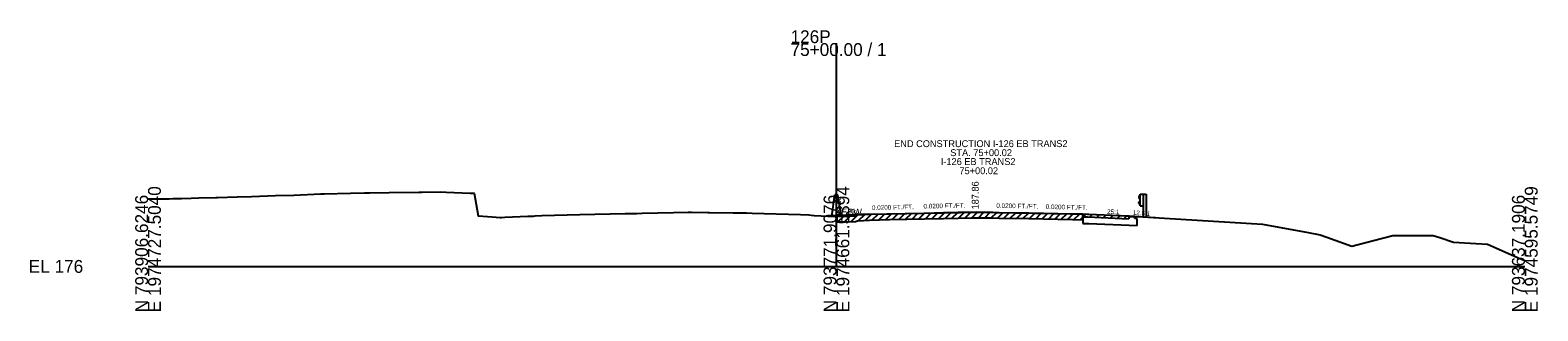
# Model space of a CAD drawing. Extents: x -161 to 1970889, y -4362 to 797231.
# Drawn here: x 2974.3 to 3302.8, y 5990.3 to 6051.5 of the extents above; entities that cross this region are included whole.
import ezdxf

# ---------------------------------------------------------------- set-up
doc = ezdxf.new("R2010")
doc.units = 0
for name, color, linetype in [('RD_GPK_XS_Cell', 7, 'Continuous'), ('RD_XS_Base', 7, 'Continuous'), ('RD_XS_EarthShd', 7, 'Continuous'), ('RD_XS_ExGround', 7, 'Continuous'), ('RD_XS_ExPaveRet', 7, 'Continuous'), ('RD_XS_GR', 7, 'Continuous'), ('RD_XS_MedBWall', 7, 'Continuous'), ('RD_XS_Misc_Line', 7, 'Continuous'), ('RD_XS_Pave', 7, 'Continuous'), ('RD_XS_PaveOvlay', 7, 'Continuous'), ('RD_XS_PaveShd', 7, 'Continuous'), ('RD_XS_TieSlope', 7, 'Continuous'), ('RD_XS_TX_Elev_EX', 7, 'Continuous'), ('RD_XS_TX_Elev_PR', 7, 'Continuous'), ('RD_XS_TX_MkPT', 7, 'Continuous'), ('RD_XS_TX_Notes', 7, 'Continuous'), ('RD_XS_TX_Profile', 7, 'Continuous'), ('RD_XS_TX_ShdSlope', 7, 'Continuous'), ('RD_XS_TX_Slope', 7, 'Continuous'), ('RD_XS_TX_Station', 7, 'Continuous')]:
    doc.layers.add(name, color=color, linetype=linetype)

msp = doc.modelspace()

# ---------------------------------------------------------------- linework, layer by layer
at = {"layer": 'RD_GPK_XS_Cell'}
for p, q in [((3150, 6000), (3150, 6048.68)), ((3000, 6000), (3150, 6000)), ((3150, 6000), (3300, 6000))]:
    msp.add_line(p, q, dxfattribs=at)
at = {"layer": 'RD_XS_Base'}
for p, q in [((3203.71, 6009.37), (3205, 6009.34)), ((3205, 6009.34), (3215.5, 6008.92)), ((3215, 6010.42), (3215, 6010.98)), ((3215.5, 6010.4), (3215, 6010.42)), ((3215.5, 6008.92), (3215.5, 6010.4))]:
    msp.add_line(p, q, dxfattribs=at)
at = {"layer": 'RD_XS_EarthShd'}
msp.add_line((3215, 6010.98), (3217, 6010.82), dxfattribs=at)
at = {"layer": 'RD_XS_ExGround'}
msp.add_lwpolyline([(3000, 6014.7), (3004.58, 6014.77), (3005.41, 6014.78), (3007.27, 6014.82), (3009.39, 6014.87), (3011.07, 6014.93), (3014.78, 6015.01), (3015.15, 6015.01), (3019.39, 6015.15), (3022.51, 6015.25), (3026.03, 6015.37), (3027.76, 6015.43), (3031.78, 6015.57), (3037.68, 6015.79), (3038.41, 6015.8), (3044.14, 6015.94), (3047.13, 6016.02), (3047.79, 6016.05), (3048.31, 6016.06), (3052.55, 6016.1), (3059.02, 6016.18), (3059.75, 6016.17), (3063.68, 6016.23), (3064.96, 6016.17), (3070.16, 6015.97), (3070.55, 6015.97), (3071.03, 6015.97), (3071.9, 6011), (3074.98, 6010.79), (3076.73, 6010.64), (3077.04, 6010.67), (3077.71, 6010.75), (3082.75, 6010.92), (3084.01, 6010.96), (3084.32, 6011.06), (3085.79, 6011.1), (3094.11, 6011.34), (3103.96, 6011.52), (3106.48, 6011.57), (3107.69, 6011.59), (3114.51, 6011.75), (3117.66, 6011.83), (3118.44, 6011.85), (3121.99, 6011.79), (3122.31, 6011.79), (3127.48, 6011.7), (3130.37, 6011.65), (3131.62, 6011.61), (3142.19, 6011.34), (3143.95, 6011.23), (3144.47, 6011.19), (3145.18, 6011.07), (3146.65, 6011.02), (3148.12, 6010.97), (3150, 6010.96), (3151.07, 6010.95), (3151.94, 6010.98), (3154.12, 6011.04), (3154.58, 6011.22), (3157.23, 6011.36), (3161.58, 6011.46), (3169.17, 6011.64), (3173.3, 6011.73), (3176.56, 6011.8), (3179.39, 6011.85), (3180.44, 6011.87), (3183.55, 6011.83), (3184.09, 6011.81), (3185.44, 6011.79), (3191.91, 6011.66), (3201.44, 6011.48), (3204.68, 6011.41), (3213.71, 6011.01), (3214.05, 6010.9), (3215.58, 6010.87), (3217.91, 6010.72), (3242.87, 6009.24), (3252.82, 6007.39), (3255.4, 6006.9), (3256.87, 6006.35), (3262.33, 6004.42), (3267, 6005.63), (3271.27, 6006.76), (3273.64, 6006.76), (3280.05, 6006.76), (3281.48, 6006.29), (3284.47, 6005.28), (3289.34, 6005.01), (3291.89, 6004.84), (3298.26, 6002.04), (3298.58, 6001.9), (3300, 6001.31)], dxfattribs=at)
at = {"layer": 'RD_XS_ExPaveRet'}
for p, q in [((3150, 6009.71), (3150, 6010.96)), ((3203.71, 6010.81), (3203.71, 6011.43)), ((3203.71, 6011.43), (3203.71, 6010.18)), ((3203.71, 6010.81), (3204.68, 6010.79)), ((3204.68, 6010.79), (3213.71, 6010.38)), ((3213.71, 6011.01), (3213.71, 6010.38)), ((3213.71, 6010.38), (3213.71, 6010.38))]:
    msp.add_line(p, q, dxfattribs=at)
msp.add_lwpolyline([(3150, 6009.71), (3150, 6009.71), (3151.07, 6009.7), (3151.94, 6009.73), (3154.12, 6009.79), (3154.58, 6009.97), (3157.23, 6010.11), (3161.58, 6010.21), (3169.17, 6010.39), (3173.3, 6010.48), (3176.56, 6010.55), (3179.39, 6010.6), (3180.44, 6010.62), (3183.55, 6010.58), (3184.09, 6010.56), (3185.44, 6010.54), (3191.91, 6010.41), (3201.44, 6010.23), (3203.71, 6010.18)], dxfattribs=at)
at = {"layer": 'RD_XS_GR'}
for p, q in [((3216.15, 6015.61), (3215.88, 6015.17)), ((3216.15, 6015.77), (3216.81, 6015.77)), ((3216.15, 6013.21), (3216.15, 6015.77)), ((3216.81, 6015.77), (3217.48, 6015.77)), ((3216.81, 6015.77), (3216.81, 6010.83)), ((3217.48, 6015.77), (3217.48, 6010.72)), ((3215.88, 6015.17), (3215.88, 6015.06)), ((3215.88, 6015.06), (3216.15, 6014.62)), ((3215.88, 6013.92), (3216.15, 6014.36)), ((3215.88, 6013.81), (3215.88, 6013.92)), ((3216.15, 6013.37), (3215.88, 6013.81)), ((3216.15, 6013.21), (3216.81, 6013.21))]:
    msp.add_line(p, q, dxfattribs=at)
at = {"layer": 'RD_XS_MedBWall'}
for p, q in [((3148.98, 6010.97), (3149.67, 6015.6)), ((3150, 6015.6), (3149.67, 6015.6)), ((3150, 6015.6), (3150.33, 6015.6)), ((3151, 6011.12), (3150.33, 6015.6))]:
    msp.add_line(p, q, dxfattribs=at)
at = {"layer": 'RD_XS_Misc_Line'}
for p, q in [((3150, 6010.8), (3150.16, 6010.96)), ((3150.32, 6009.71), (3151.58, 6010.97)), ((3151.75, 6009.72), (3153.04, 6011.01)), ((3153.21, 6009.77), (3154.67, 6011.23)), ((3154.84, 6009.98), (3156.16, 6011.3)), ((3156.33, 6010.06), (3157.63, 6011.37)), ((3157.8, 6010.12), (3159.08, 6011.4)), ((3159.25, 6010.15), (3160.53, 6011.43)), ((3160.7, 6010.19), (3161.98, 6011.47)), ((3162.15, 6010.22), (3163.43, 6011.5)), ((3163.6, 6010.26), (3164.88, 6011.54)), ((3165.05, 6010.29), (3166.32, 6011.57)), ((3166.49, 6010.32), (3167.76, 6011.6)), ((3167.94, 6010.36), (3169.21, 6011.62)), ((3169.39, 6010.39), (3170.65, 6011.65)), ((3170.84, 6010.42), (3172.09, 6011.68)), ((3172.28, 6010.46), (3173.54, 6011.71)), ((3173.73, 6010.49), (3174.98, 6011.74)), ((3175.17, 6010.52), (3176.42, 6011.77)), ((3176.62, 6010.55), (3177.87, 6011.8)), ((3178.06, 6010.57), (3179.31, 6011.83)), ((3179.5, 6010.6), (3180.75, 6011.86)), ((3180.92, 6010.61), (3182.15, 6011.84)), ((3182.32, 6010.59), (3183.53, 6011.81)), ((3183.71, 6010.57), (3184.92, 6011.78)), ((3185.1, 6010.54), (3186.31, 6011.75)), ((3186.48, 6010.52), (3187.69, 6011.73)), ((3187.87, 6010.49), (3189.08, 6011.7)), ((3189.26, 6010.46), (3190.47, 6011.67)), ((3190.64, 6010.43), (3191.85, 6011.64)), ((3192.03, 6010.4), (3193.24, 6011.62)), ((3193.42, 6010.38), (3194.63, 6011.59)), ((3194.8, 6010.35), (3196.01, 6011.56)), ((3196.19, 6010.32), (3197.4, 6011.53)), ((3197.58, 6010.3), (3198.79, 6011.5)), ((3198.97, 6010.27), (3200.17, 6011.48)), ((3200.36, 6010.25), (3201.56, 6011.45)), ((3201.74, 6010.22), (3202.95, 6011.42)), ((3203.13, 6010.19), (3203.71, 6010.77)), ((3203.71, 6010.81), (3204.33, 6011.42)), ((3205.21, 6010.76), (3205.81, 6011.36)), ((3206.71, 6010.7), (3207.31, 6011.3)), ((3208.21, 6010.63), (3208.81, 6011.23)), ((3209.71, 6010.56), (3210.31, 6011.16)), ((3211.21, 6010.49), (3211.81, 6011.09)), ((3212.71, 6010.43), (3213.31, 6011.02))]:
    msp.add_line(p, q, dxfattribs=at)
at = {"layer": 'RD_XS_Pave'}
for p, q in [((3157, 6011.38), (3181, 6011.86)), ((3181, 6011.86), (3205, 6011.38))]:
    msp.add_line(p, q, dxfattribs=at)
at = {"layer": 'RD_XS_PaveOvlay'}
msp.add_line((3203.71, 6011.43), (3203.71, 6009.37), dxfattribs=at)
msp.add_lwpolyline([(3150, 6010.96), (3151.07, 6010.95), (3151.94, 6010.98), (3154.12, 6011.04), (3154.58, 6011.22), (3157.23, 6011.36), (3161.58, 6011.46), (3169.17, 6011.64), (3173.3, 6011.73), (3176.56, 6011.8), (3179.39, 6011.85), (3180.44, 6011.87), (3183.55, 6011.83), (3184.09, 6011.81), (3185.44, 6011.79), (3191.91, 6011.66), (3201.44, 6011.48), (3203.71, 6011.43)], dxfattribs=at)
at = {"layer": 'RD_XS_PaveShd'}
for p, q in [((3157, 6011.38), (3148.99, 6011.06)), ((3205, 6011.38), (3215, 6010.98))]:
    msp.add_line(p, q, dxfattribs=at)
at = {"layer": 'RD_XS_TieSlope'}
msp.add_line((3216, 6010.9), (3219.49, 6010.63), dxfattribs=at)

# ---------------------------------------------------------------- texts
at = {"layer": 'RD_GPK_XS_Cell'}
for s, p in [('75+00.00 / 1', (3140, 6045.88)), ('126P', (3140, 6048.68)), ('EL 176', (2974, 5998.6))]:
    msp.add_text(s, height=2.8, dxfattribs=at).set_placement(p)
for s, p in [('N 793906.6246', (3000, 5990)), ('E 1974727.5040', (3002.8, 5990)), ('N 793771.9076', (3150, 5990)), ('E 1974661.5394', (3152.8, 5990)), ('N 793637.1906', (3300, 5990)), ('E 1974595.5749', (3302.8, 5990))]:
    msp.add_text(s, height=2.8, rotation=90, dxfattribs=at).set_placement(p)
at = {"layer": 'RD_XS_ExGround'}
msp.add_text('186.96', height=1, rotation=90, dxfattribs=at).set_placement((3150.96, 6010.97))
at = {"layer": 'RD_XS_TX_Elev_EX'}
msp.add_text('186.96', height=1, rotation=90, dxfattribs=at).set_placement((3151, 6010.96))
at = {"layer": 'RD_XS_TX_Elev_PR'}
msp.add_text(' 187.86', height=1.5, rotation=90, dxfattribs=at).set_placement((3181, 6011.86))
at = {"layer": 'RD_XS_TX_MkPT'}
msp.add_text('EBW', height=1.5, dxfattribs=at).set_placement((3151, 6011.12))
at = {"layer": 'RD_XS_TX_Notes'}
for s, p in [('END CONSTRUCTION I-126 EB TRANS2', (3162.57, 6026.01)), ('STA. 75+00.02', (3174.81, 6024.05))]:
    msp.add_text(s, height=1.5, dxfattribs=at).set_placement(p)
at = {"layer": 'RD_XS_TX_Profile'}
for rotation, p in [(2.2906, (3152.44, 6011.45)), (357.7094, (3208.96, 6011.47))]:
    msp.add_text('25:1', height=1, rotation=rotation, dxfattribs=at).set_placement(p)
at = {"layer": 'RD_XS_TX_ShdSlope'}
msp.add_text('12.5:1', height=1, rotation=355.4261, dxfattribs=at).set_placement((3214.54, 6011.27))
at = {"layer": 'RD_XS_TX_Slope'}
for rotation, p in [(1.1458, (3157.74, 6012.3)), (1.1458, (3168.98, 6012.62)), (358.8542, (3184.83, 6012.78)), (358.5681, (3195.59, 6012.54))]:
    msp.add_text('0.0200 FT./FT.', height=1, rotation=rotation, dxfattribs=at).set_placement(p)
at = {"layer": 'RD_XS_TX_Station'}
for s, p in [('I-126 EB TRANS2', (3172.74, 6022.11)), ('75+00.02', (3176.8, 6020.11))]:
    msp.add_text(s, height=1.5, dxfattribs=at).set_placement(p)

doc.saveas('drawing.dxf')
